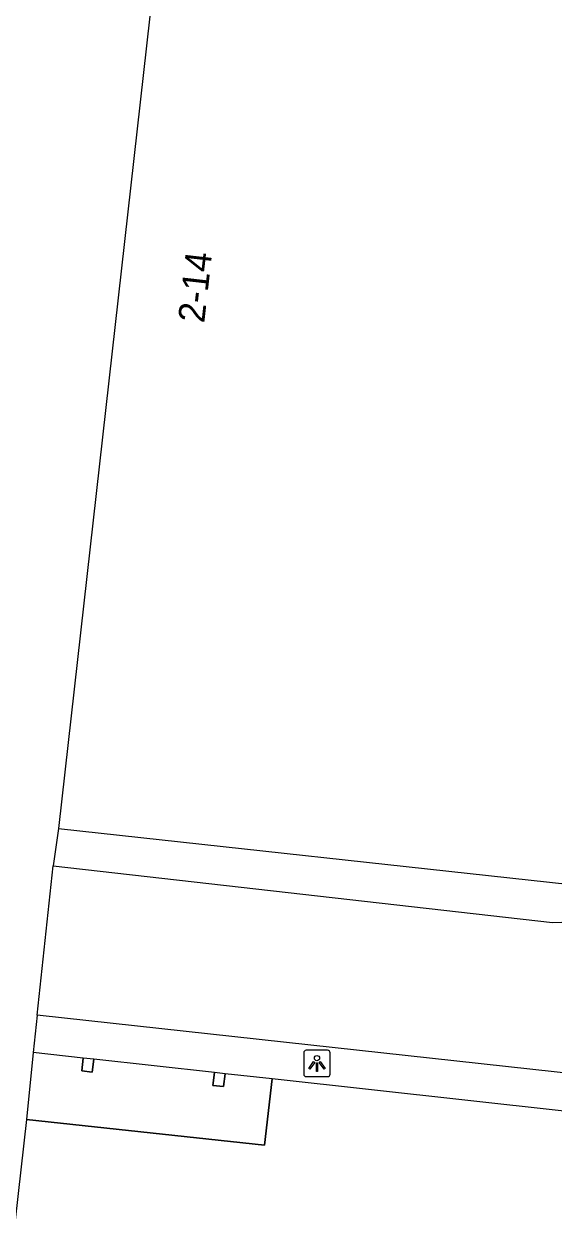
# Model space of a CAD drawing. Extents: x 162026 to 163499, y 387297 to 388169.
# Drawn here: x 162278.4 to 162298.48, y 387569.33 to 387614.96 of the extents above; entities that cross this region are included whole.
import ezdxf

# ---------------------------------------------------------------- set-up
doc = ezdxf.new("R2010")
doc.units = 0
for name, color, linetype in [('IMGEO_Lichtpunt', 7, 'Continuous'), ('IMGEO_Pand', 7, 'Continuous'), ('IMGEO_Pand_nummerreeks', 7, 'Continuous'), ('IMGEO_Pand_overbouw', 7, 'Continuous'), ('IMGEO_Rijbaan_lokaal_open', 7, 'Continuous'), ('IMGEO_Voetpad_open', 7, 'Continuous')]:
    doc.layers.add(name, color=color, linetype=linetype)

msp = doc.modelspace()

# ---------------------------------------------------------------- linework, layer by layer
at = {"layer": 'IMGEO_Lichtpunt'}
for p, q in [((162289.001, 387575.97), (162289.001, 387575.163)), ((162289.001, 387575.97), (162289.001, 387575.163)), ((162289.903, 387576.065), (162289.095, 387576.065)), ((162289.903, 387576.065), (162289.095, 387576.065)), ((162289.997, 387575.163), (162289.997, 387575.97)), ((162289.997, 387575.163), (162289.997, 387575.97)), ((162289.095, 387575.069), (162289.903, 387575.069)), ((162289.095, 387575.069), (162289.903, 387575.069))]:
    msp.add_line(p, q, dxfattribs=at)
for points in [[(162289.375, 387575.634), (162289.414, 387575.606), (162289.226, 387575.344), (162289.188, 387575.371), (162289.375, 387575.634)], [(162289.477, 387575.586), (162289.524, 387575.586), (162289.524, 387575.264), (162289.477, 387575.264), (162289.477, 387575.586)], [(162289.587, 387575.606), (162289.625, 387575.633), (162289.812, 387575.371), (162289.773, 387575.343), (162289.587, 387575.606)]]:
    msp.add_lwpolyline(points, dxfattribs=at)
msp.add_circle((162289.5, 387575.768), 0.0994, dxfattribs=at)
for centre, start, end in [((162289.095, 387575.97), 90, 180), ((162289.095, 387575.97), 90, 180), ((162289.903, 387575.97), 0, 90), ((162289.903, 387575.97), 0, 90), ((162289.095, 387575.163), 180, 270), ((162289.095, 387575.163), 180, 270), ((162289.903, 387575.163), 270, 0), ((162289.903, 387575.163), 270, 360)]:
    msp.add_arc(centre, 0.0946, start, end, dxfattribs=at)
at = {"layer": 'IMGEO_Pand'}
for points in [[(162284.468, 387626.843), (162279.706, 387584.469)], [(162279.706, 387584.469), (162299.117, 387582.352), (162301.839, 387606.644)], [(162280.642, 387575.768), (162280.585, 387575.282), (162280.983, 387575.238), (162281.039, 387575.724), (162280.642, 387575.768)], [(162285.611, 387575.218), (162285.555, 387574.731), (162285.962, 387574.686), (162286.019, 387575.173), (162285.611, 387575.218)], [(162328.303, 387570.491), (162287.798, 387574.976), (162287.507, 387572.471), (162278.491, 387573.437)], [(162278.491, 387573.437), (162276.745, 387558.061)]]:
    msp.add_lwpolyline(points, dxfattribs=at)
at = {"layer": 'IMGEO_Pand_overbouw'}
msp.add_lwpolyline([(162287.798, 387574.976), (162286.019, 387575.173), (162285.962, 387574.686), (162285.555, 387574.731), (162285.611, 387575.218), (162281.039, 387575.724), (162280.983, 387575.238), (162280.585, 387575.282), (162280.642, 387575.768), (162278.751, 387575.978), (162278.491, 387573.437), (162287.507, 387572.471)], close=True, dxfattribs=at)
at = {"layer": 'IMGEO_Rijbaan_lokaal_open'}
for points in [[(162278.897, 387577.398), (162279.501, 387583.06)], [(162279.501, 387583.06), (162298.426, 387580.903), (162299.127, 387580.938)], [(162328.303, 387570.491), (162328.456, 387571.969), (162278.897, 387577.398)]]:
    msp.add_lwpolyline(points, dxfattribs=at)
at = {"layer": 'IMGEO_Voetpad_open'}
for points in [[(162279.706, 387584.469), (162279.501, 387583.06)], [(162278.897, 387577.398), (162278.751, 387575.978), (162278.491, 387573.437)]]:
    msp.add_lwpolyline(points, dxfattribs=at)

# ---------------------------------------------------------------- texts
at = {"layer": 'IMGEO_Pand_nummerreeks'}
msp.add_text('2-14', height=1, rotation=83.5315, dxfattribs=at).set_placement((162285.226, 387603.605))

doc.saveas('drawing.dxf')
